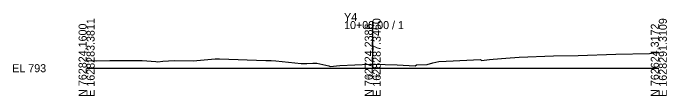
# Model space of a CAD drawing. Extents: x -26 to 203, y -10 to 3017.
# Drawn here: x -25.7 to 202.8, y -9.7 to 19.3 of the extents above; entities that cross this region are included whole.
import ezdxf

# ---------------------------------------------------------------- set-up
doc = ezdxf.new("R2010")
doc.units = 0
for name, color, linetype in [('Default', 7, 'Continuous'), ('Exist Cross Section Cell', 7, 'Continuous'), ('Exist XS Center Line Elevation Label', 7, 'Continuous'), ('Exist XS Ground Line', 7, 'Continuous')]:
    doc.layers.add(name, color=color, linetype=linetype)

msp = doc.modelspace()

# ---------------------------------------------------------------- linework, layer by layer
at = {"layer": 'Exist Cross Section Cell'}
for p, q in [((100, 0), (100, 16.48)), ((0, 0), (100, 0)), ((100, 0), (200, 0))]:
    msp.add_line(p, q, dxfattribs=at)
at = {"layer": 'Exist XS Ground Line'}
msp.add_lwpolyline([(0, 2.65), (3.41, 2.58), (8.13, 2.65), (15.92, 2.71), (19.38, 2.69), (24.17, 2.33), (24.85, 2.27), (26.7, 2.51), (30.61, 2.71), (37.31, 2.6), (44.95, 3.26), (46.51, 3.22), (62.68, 2.74), (64.56, 2.7), (66.15, 2.57), (74.95, 1.66), (76.99, 1.69), (79.06, 1.78), (80.42, 1.79), (84.65, 0.87), (85.15, 0.65), (88.56, 0.94), (98.99, 1.38), (99.36, 1.4), (100.21, 1.39), (108.5, 1.17), (110.64, 1.11), (114.84, 0.84), (115.35, 1.22), (118.89, 1.26), (118.99, 1.3), (121.01, 1.9), (123.14, 2.38), (125.67, 2.46), (137.7, 3.07), (138.06, 2.73), (140.82, 3.07), (142.14, 3.14), (146.53, 3.46), (151.19, 3.88), (163.19, 4.29), (171.87, 4.46), (185.02, 4.9), (196.72, 5.15), (199.02, 5.49), (200, 5.49)], dxfattribs=at)

# ---------------------------------------------------------------- texts
at = {"layer": 'Default'}
msp.add_text('-', height=0.0001, dxfattribs=at).set_placement((0, 0))
at = {"layer": 'Exist Cross Section Cell'}
for s, p in [('Y4', (90, 16.48)), ('10+00.00 / 1', (90, 13.68)), ('EL 793', (-26, -1.4))]:
    msp.add_text(s, height=2.8, dxfattribs=at).set_placement(p)
for s, p in [('E 1628283.3811', (2.8, -10)), ('E 1628287.3460', (102.8, -10)), ('E 1628291.3109', (202.8, -10)), ('N 762824.1600', (0, -10)), ('N 762724.2386', (100, -10)), ('N 762624.3172', (200, -10))]:
    msp.add_text(s, height=2.8, rotation=90, dxfattribs=at).set_placement(p)
at = {"layer": 'Exist XS Center Line Elevation Label'}
msp.add_text('794.40', height=1.2, dxfattribs=at).set_placement((97.52, -3.2))

doc.saveas('drawing.dxf')
